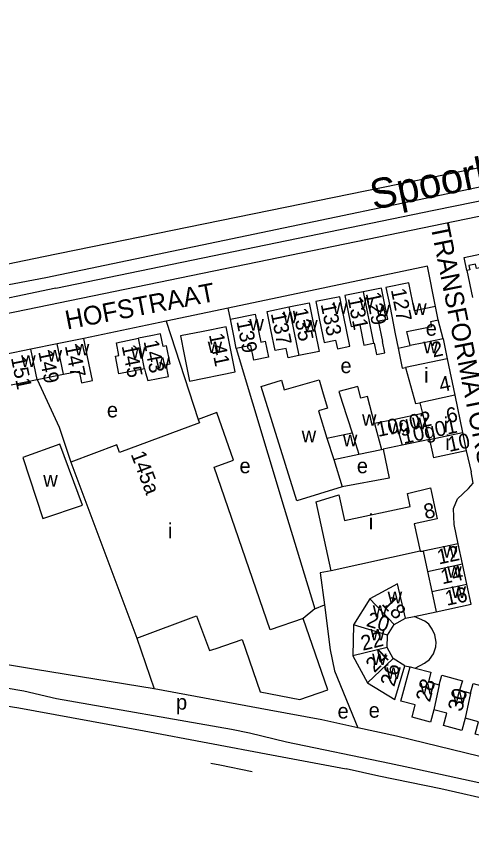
# Model space of a CAD drawing. Extents: x 163026 to 166241, y 382475 to 384501.
# Drawn here: x 163464.1 to 163585.6, y 383911.1 to 384127 of the extents above; entities that cross this region are included whole.
import ezdxf

# ---------------------------------------------------------------- set-up
doc = ezdxf.new("R2010")
doc.units = 0
for name, color, linetype in [('BLT_Basislijn', 7, 'Continuous'), ('BLT_Bebouwing', 7, 'Continuous'), ('BLT_Centroide', 7, 'Continuous'), ('BLT_Huisnummer', 7, 'Continuous'), ('BLT_Huisnummer_ tussenligend', 7, 'Continuous'), ('BLT_Onderverdeling_panden', 7, 'Continuous'), ('BLT_Spoorlijn', 7, 'Continuous'), ('BLT_Straatnaam', 7, 'Continuous'), ('BLT_Waternaam_spoorwegen', 7, 'Continuous')]:
    doc.layers.add(name, color=color, linetype=linetype)

msp = doc.modelspace()

# ---------------------------------------------------------------- linework, layer by layer
at = {"layer": 'BLT_Basislijn'}
for p, q in [((163521.21, 384046.18), (163520.65, 384049.15)), ((163504.05, 384045.65), (163512.63, 384019.46)), ((163469.68, 384030.08), (163475.57, 384017.43)), ((163475.57, 384017.43), (163478.66, 384008.08)), ((163584.08, 384011.09), (163585.37, 384005.44)), ((163571.83, 383984.31), (163572.64, 383984.32)), ((163543.7, 383968.9), (163540.6, 383966.35)), ((163543.7, 383968.9), (163546.28, 383969.97)), ((163567.93, 383966.44), (163570.17, 383966.91)), ((163570.17, 383966.91), (163576.08, 383968.16)), ((163496.3, 383961.1), (163500.93, 383947.56)), ((163469.23, 383952.75), (163444.91, 383956.73)), ((163567.76, 383953.74), (163569.15, 383953.49)), ((163500.93, 383947.56), (163469.23, 383952.75)), ((163531.59, 383941.89), (163500.93, 383947.56))]:
    msp.add_line(p, q, dxfattribs=at)
for points in [[(163842.68, 384126.99), (163680.68, 384092.81), (163440.33, 384043.29)], [(163474.67, 384054.48), (163575.47, 384075.23), (163641.5, 384088.72)], [(163584.25, 384059.18), (163583.57, 384062.68), (163624.54, 384071.33)], [(163575.93, 384049.53), (163573.78, 384060.35), (163520.65, 384049.15)], [(163474.67, 384054.48), (163451.77, 384049.7), (163439.12, 384047.21), (163407.52, 384038.82), (163390.43, 384033.42)], [(163520.65, 384049.15), (163504.05, 384045.65)], [(163504.05, 384045.65), (163482.16, 384041.04)], [(163577.9, 384040.96), (163576.65, 384045.97)], [(163522.79, 384038.35), (163535.59, 383995.75), (163543.7, 383968.9)], [(163561.95, 384011.52), (163563.58, 384003.78), (163551.03, 384001.49)], [(163581.97, 383986.3), (163580.89, 383991.39), (163580.74, 383995.66), (163581.74, 383998.26), (163584.74, 384001.06), (163585.94, 384002.46), (163585.37, 384005.44)], [(163548.09, 383979.11), (163545.16, 383978.51), (163546.28, 383969.97)], [(163702.63, 383893.66), (163670.29, 383902.93), (163634.67, 383911.51), (163596.82, 383920.18), (163593.55, 383921.19), (163569.06, 383926.52), (163563.66, 383927.7), (163536.19, 383933.37), (163526.3, 383935.81), (163521.54, 383936.78), (163474.81, 383944.9), (163466.18, 383946.96), (163461.45, 383947.79), (163451.16, 383948.61), (163417.08, 383954.66), (163407.65, 383956.71), (163387.33, 383959.28), (163383.13, 383958.87), (163346.8, 383964.76), (163292.07, 383972.41), (163284.82, 383973.83)], [(163546.28, 383969.97), (163547.84, 383958.02), (163548.98, 383952.43), (163555.21, 383937.21)], [(163570.52, 383953.12), (163572.95, 383954.41), (163574.3, 383955.46), (163575.38, 383956.91), (163576, 383958.82), (163576.05, 383960.01), (163575.74, 383962.03), (163575.02, 383963.53), (163574.14, 383964.82), (163573.02, 383965.65), (163570.17, 383966.91)], [(163555.21, 383937.21), (163545.6, 383939.31), (163531.59, 383941.89)], [(163613.23, 383923.33), (163565.51, 383934.95), (163555.21, 383937.21)]]:
    msp.add_lwpolyline(points, dxfattribs=at)
at = {"layer": 'BLT_Bebouwing'}
for p, q in [((163584.25, 384059.18), (163585.75, 384051.96)), ((163482.16, 384041.04), (163475.04, 384039.6)), ((163577.9, 384040.96), (163579.02, 384035.59)), ((163468.04, 384038.18), (163461.17, 384036.79)), ((163475.04, 384039.6), (163468.04, 384038.18)), ((163565.96, 384038.49), (163567.05, 384033.11)), ((163579.02, 384035.59), (163581.04, 384025.89)), ((163567.05, 384033.11), (163567.86, 384033.27)), ((163462.79, 384028.68), (163469.68, 384030.08)), ((163581.04, 384025.89), (163583.09, 384015.95)), ((163571.68, 384023.9), (163572.44, 384021.02)), ((163574.29, 384014.11), (163567.05, 384012.59)), ((163574.29, 384014.11), (163575.35, 384009.19)), ((163583.09, 384015.95), (163584.08, 384011.09)), ((163567.05, 384012.59), (163561.95, 384011.52)), ((163584.08, 384011.09), (163575.35, 384009.19)), ((163478.66, 384008.08), (163496.3, 383961.1)), ((163548.09, 383979.11), (163544.11, 383997.43)), ((163581.97, 383986.3), (163572.64, 383984.32)), ((163583.12, 383980.9), (163581.97, 383986.3)), ((163572.64, 383984.32), (163573.79, 383978.92)), ((163584.27, 383975.52), (163583.12, 383980.9)), ((163573.79, 383978.92), (163574.93, 383973.54)), ((163574.93, 383973.54), (163576.08, 383968.16)), ((163558.36, 383971.62), (163554.08, 383964.63)), ((163564.86, 383964.77), (163567.93, 383966.44)), ((163554.08, 383964.63), (163553.87, 383956.43)), ((163563.13, 383961.95), (163564.86, 383964.77)), ((163563.05, 383958.63), (163563.13, 383961.95)), ((163564.62, 383955.72), (163563.05, 383958.63)), ((163553.87, 383956.43), (163557.78, 383949.22))]:
    msp.add_line(p, q, dxfattribs=at)
for points in [[(163590.59, 384060.5), (163586.79, 384059.71), (163586.55, 384060.86), (163584.79, 384060.49), (163585.03, 384059.35), (163584.25, 384059.18)], [(163575.93, 384049.53), (163570.28, 384048.39), (163568.76, 384055.89), (163562.68, 384054.66), (163563.68, 384049.76), (163564.24, 384046.97), (163565.18, 384042.32), (163565.96, 384038.49)], [(163556.61, 384053.45), (163551.74, 384052.47), (163552.73, 384047.57), (163553.41, 384044.23)], [(163559.39, 384039.78), (163559.57, 384039.82), (163560.19, 384036.75), (163562.38, 384037.19), (163561.76, 384040.26), (163561.83, 384040.27), (163560.73, 384045.72), (163563.17, 384046.23), (163562.48, 384049.54), (163561.49, 384054.44), (163556.61, 384053.45)], [(163551.38, 384047.28), (163550.39, 384052.18), (163543.99, 384050.89), (163544.99, 384045.95), (163546.2, 384040), (163549.27, 384040.63), (163549.74, 384038.31), (163553.06, 384038.98), (163551.38, 384047.28)], [(163539.45, 384036.48), (163536.6, 384035.9), (163536.09, 384038.39), (163533.16, 384037.79), (163532.02, 384043.37), (163531.03, 384048.27), (163536.83, 384049.45)], [(163536.83, 384049.45), (163542.2, 384050.54), (163543.2, 384045.64), (163543.8, 384042.82), (163544.86, 384037.57), (163539.45, 384036.48)], [(163576.65, 384045.97), (163575.93, 384049.53)], [(163521.21, 384046.18), (163527.79, 384047.51), (163528.79, 384042.61)], [(163510.35, 384029.68), (163522.52, 384032.15), (163520.09, 384044.18), (163513.99, 384042.94)], [(163522.79, 384038.35), (163522.2, 384041.28), (163521.21, 384046.18)], [(163553.41, 384044.23), (163555.73, 384044.7), (163556.83, 384039.26), (163559.39, 384039.78)], [(163569.16, 384039.15), (163568.3, 384042.93), (163574.96, 384044.25), (163574.69, 384045.58), (163576.65, 384045.97)], [(163498.32, 384032.94), (163498.54, 384031.86), (163499.19, 384029.8), (163504.74, 384030.93), (163504.1, 384034.07), (163505.18, 384034.32), (163504.21, 384039.11), (163503.25, 384038.92), (163502.58, 384042.28), (163500, 384041.75), (163496.68, 384041.08)], [(163513.99, 384042.94), (163507.89, 384041.71), (163508.88, 384036.81), (163510.35, 384029.68)], [(163528.79, 384042.61), (163529.3, 384040.07), (163530.47, 384040.3), (163531.34, 384036.03), (163527.48, 384035.25), (163526.69, 384039.14), (163522.79, 384038.35)], [(163476.7, 384031.5), (163480.89, 384032.35), (163481.52, 384029.23), (163484.45, 384029.83), (163483.15, 384036.14), (163482.16, 384041.04)], [(163498.32, 384032.94), (163491.5, 384031.6), (163490.55, 384036.32), (163491.49, 384036.52), (163490.81, 384039.89), (163496.68, 384041.08)], [(163577.9, 384040.96), (163572.78, 384039.89), (163569.16, 384039.15)], [(163469.68, 384030.08), (163476.7, 384031.5)], [(163567.86, 384033.27), (163570.61, 384023.68), (163571.68, 384023.9)], [(163551.03, 384001.49), (163538.95, 383997.7), (163529.39, 384028.2), (163534.82, 384029.9), (163535.57, 384027.3), (163544.88, 384030.01), (163545.97, 384026.3), (163547.11, 384022.42), (163544.7, 384021.71), (163546.96, 384014.47)], [(163559.67, 384018.33), (163557.74, 384025.58), (163556, 384025.12), (163555.18, 384028.24), (163550.11, 384026.9), (163551.1, 384023.82), (163553.66, 384015.88)], [(163531.84, 383963.34), (163516.9, 384006.73), (163522.07, 384008.55), (163517.6, 384021.33), (163512.63, 384019.46)], [(163572.44, 384021.02), (163565.05, 384019.46)], [(163512.63, 384019.46), (163512.98, 384018.51), (163491.68, 384010.61), (163490.93, 384012.64), (163478.66, 384008.08)], [(163565.05, 384019.46), (163559.67, 384018.33)], [(163546.96, 384014.47), (163553.66, 384015.88)], [(163548.76, 384008.74), (163555.47, 384010.15)], [(163555.47, 384010.15), (163561.53, 384011.43)], [(163561.53, 384011.43), (163561.95, 384011.52)], [(163548.76, 384008.74), (163551.03, 384001.49)], [(163569.15, 383996.24), (163568.41, 383999.73), (163574.55, 384001.18), (163574.8, 384000), (163576.31, 383992.96), (163570.25, 383991.63)], [(163544.11, 383997.43), (163550.13, 383999.35)], [(163550.13, 383999.35), (163551.64, 383992.46), (163569.15, 383996.24)], [(163570.25, 383991.63), (163571.83, 383984.31)], [(163571.83, 383984.31), (163548.09, 383979.11)], [(163567.93, 383966.44), (163565.73, 383975.61), (163558.36, 383971.62)], [(163576.08, 383968.16), (163585.41, 383970.14), (163584.27, 383975.52)], [(163496.3, 383961.1), (163512.19, 383967.07), (163515.66, 383957.79)], [(163524.31, 383960.76), (163529.17, 383946.76), (163539.71, 383944.77), (163547.21, 383947.34), (163540.6, 383966.35)], [(163540.6, 383966.35), (163531.84, 383963.34)], [(163517.39, 383958.39), (163524.31, 383960.76)], [(163515.66, 383957.79), (163517.39, 383958.39)], [(163567.76, 383953.74), (163564.62, 383955.72)], [(163557.78, 383949.22), (163565.02, 383944.72), (163567.76, 383953.74)], [(163575.42, 383942.02), (163574.53, 383938.73), (163569.67, 383940.04), (163570.52, 383943.33), (163566.7, 383944.35), (163569.15, 383953.49)], [(163569.15, 383953.49), (163570.52, 383953.12)], [(163570.52, 383953.12), (163574.68, 383952.01)], [(163574.68, 383952.01), (163574.03, 383949.46), (163576.87, 383948.69)], [(163576.87, 383948.69), (163577.55, 383951.24), (163583.06, 383949.76), (163582.33, 383947.23), (163585.26, 383946.44)], [(163585.26, 383946.44), (163585.94, 383948.99), (163591.47, 383947.52), (163590.78, 383944.97), (163593.66, 383944.19)], [(163583.82, 383939.77), (163582.94, 383936.48), (163578.06, 383937.78), (163578.94, 383941.08), (163575.42, 383942.02)], [(163592.21, 383937.53), (163591.33, 383934.23), (163586.46, 383935.54), (163587.34, 383938.83), (163583.82, 383939.77)]]:
    msp.add_lwpolyline(points, dxfattribs=at)
msp.add_lwpolyline([(163475.73, 384012.88), (163465.84, 384009.28), (163471.24, 383993.07), (163481.77, 383996.58)], close=True, dxfattribs=at)
at = {"layer": 'BLT_Onderverdeling_panden'}
for p, q in [((163556.61, 384053.45), (163559.39, 384039.78)), ((163536.83, 384049.45), (163539.45, 384036.48)), ((163498.32, 384032.94), (163496.68, 384041.08)), ((163469.68, 384030.08), (163468.04, 384038.18)), ((163565.96, 384038.49), (163569.16, 384039.15)), ((163579.02, 384035.59), (163567.86, 384033.27)), ((163581.04, 384025.89), (163571.68, 384023.9)), ((163572.44, 384021.02), (163574.29, 384014.11)), ((163559.67, 384018.33), (163561.53, 384011.43)), ((163565.05, 384019.46), (163567.05, 384012.59)), ((163546.96, 384014.47), (163548.76, 384008.74)), ((163553.66, 384015.88), (163555.47, 384010.15)), ((163574.29, 384014.11), (163583.09, 384015.95)), ((163573.79, 383978.92), (163583.12, 383980.9)), ((163574.93, 383973.54), (163584.27, 383975.52)), ((163558.36, 383971.62), (163564.86, 383964.77)), ((163563.13, 383961.95), (163554.08, 383964.63)), ((163563.05, 383958.63), (163553.87, 383956.43)), ((163564.62, 383955.72), (163557.78, 383949.22)), ((163576.87, 383948.69), (163575.42, 383942.02)), ((163585.26, 383946.44), (163583.82, 383939.77))]:
    msp.add_line(p, q, dxfattribs=at)
msp.add_lwpolyline([(163476.7, 384031.5), (163475.04, 384039.6)], dxfattribs=at)
at = {"layer": 'BLT_Spoorlijn'}
for points in [[(163639.01, 384097.02), (163471.35, 384062.78)], [(163640.46, 384092.45), (163471.97, 384057.17)], [(163471.35, 384062.78), (163412.99, 384050.74), (163389.98, 384046.06)], [(163471.97, 384057.17), (163430.18, 384049.33), (163384.3, 384039.79), (163316.56, 384025.59), (163276.72, 384017.68), (163250.47, 384013.02), (163229.43, 384009.69)], [(163350, 383960.93), (163369.89, 383957.65), (163402.55, 383952.6), (163433.53, 383947.55), (163464.85, 383942.49), (163498.18, 383936.43), (163532.19, 383930.03), (163552.1, 383926.26)], [(163516, 383927.75), (163518.39, 383927.33), (163526.98, 383925.52)], [(163693.96, 383892.62), (163677.32, 383896.67), (163644.66, 383905.43), (163614.36, 383912.5), (163603.9, 383915.03), (163592.13, 383917.56), (163577.31, 383920.93), (163560.81, 383924.3), (163552.1, 383926.26)]]:
    msp.add_lwpolyline(points, dxfattribs=at)

# ---------------------------------------------------------------- texts
at = {"layer": 'BLT_Centroide'}
for s, p in [('w', (163548.53, 384047.59)), ('w', (163555.56, 384048.95)), ('w', (163559.89, 384047)), ('w', (163569.67, 384047.31)), ('w', (163535.23, 384045.11)), ('w', (163526.27, 384043.14)), ('w', (163540.61, 384042.88)), ('e', (163573.3, 384041.77)), ('w', (163515.16, 384037.16)), ('w', (163572.68, 384037.09)), ('w', (163472.48, 384034.88)), ('w', (163479.73, 384036.5)), ('w', (163494.73, 384035.62)), ('w', (163465.42, 384033.44)), ('w', (163501.16, 384032.98)), ('e', (163550.56, 384031.8)), ('i', (163572.85, 384029.25)), ('e', (163488.29, 384019.99)), ('w', (163556.31, 384017.77)), ('w', (163563.36, 384015.45)), ('w', (163569.66, 384016.81)), ('i', (163578.09, 384016.03)), ('w', (163540.22, 384013.38)), ('w', (163551.21, 384012.31)), ('i', (163578.51, 384011.3)), ('e', (163523.64, 384005.1)), ('e', (163554.93, 384005.1)), ('w', (163471.32, 384001.52)), ('i', (163558.12, 383990.16)), ('i', (163504.55, 383987.75)), ('w', (163577.88, 383982.62)), ('w', (163579.03, 383977.22)), ('w', (163563.14, 383970.41)), ('w', (163580.17, 383971.84)), ('w', (163559.18, 383966.78)), ('w', (163558.53, 383960.53)), ('w', (163558.98, 383953.94)), ('w', (163562.77, 383950.22)), ('w', (163571.78, 383946.12)), ('p', (163506.72, 383942.05)), ('w', (163580.34, 383943.84)), ('e', (163549.79, 383939.69)), ('e', (163558.08, 383939.9))]:
    msp.add_text(s, height=4, dxfattribs=at).set_placement(p)
at = {"layer": 'BLT_Huisnummer'}
for s, rotation, p in [('127', 281.4521, (163563.98, 384054.02)), ('131', 281.4616, (163552.43, 384051.78)), ('135', 281.4663, (163537.79, 384048.76)), ('139', 281.4643, (163522.81, 384045.6)), ('141', 281.4628, (163515.46, 384042.05)), ('143', 281.4571, (163498.05, 384040.27)), ('2', 11.7117, (163575.28, 384035.97)), ('147', 281.4654, (163477.04, 384039.07)), ('145', 281.4591, (163492.2, 384039.04)), ('6', 11.7145, (163579.19, 384018.42)), ('10g02', 12.0671, (163560.61, 384014.77)), ('10g01', 12.0671, (163567.42, 384012.9)), ('10', 12.0671, (163579.58, 384010.77)), ('145a', 290.8557, (163494.59, 384010.17)), ('8', 12.0671, (163573.22, 383992.82)), ('12', 11.9979, (163576.77, 383980.75)), ('16', 12.005, (163578.9, 383969.73)), ('18', 313.498, (163561.37, 383970.12)), ('22', 13.5019, (163556.51, 383957.74)), ('26', 73.5635, (163564.89, 383947.98)), ('28', 75.1096, (163574.4, 383943.88))]:
    msp.add_text(s, height=4, rotation=rotation, dxfattribs=at).set_placement(p)
at = {"layer": 'BLT_Huisnummer_ tussenligend'}
for s, rotation, p in [('129', 281.4521, (163557.28, 384053.04)), ('133', 281.4616, (163545.26, 384050.18)), ('137', 281.4663, (163531.96, 384047.71)), ('149', 281.4654, (163469.96, 384037.51)), ('151', 281.4654, (163462.68, 384035.9)), ('4', 11.7117, (163577.3, 384026.68)), ('14', 12.0037, (163577.73, 383975.48)), ('20', 343.4978, (163557.21, 383964.4)), ('24', 43.5541, (163559.6, 383951.75)), ('30', 75.1113, (163582.94, 383941.35))]:
    msp.add_text(s, height=4, rotation=rotation, dxfattribs=at).set_placement(p)
at = {"layer": 'BLT_Straatnaam'}
for s, height, rotation, p in [('TRANSFORMATORSTRAAT', 4.9999, 281.3104, (163574.58, 384071)), ('HOFSTRAAT', 5, 10.8754, (163477.67, 384043.41))]:
    msp.add_text(s, height=height, rotation=rotation, dxfattribs=at).set_placement(p)
at = {"layer": 'BLT_Waternaam_spoorwegen'}
msp.add_text('Spoorlijn', height=8, rotation=11.806, dxfattribs=at).set_placement((163559.38, 384075.31))

doc.saveas('drawing.dxf')
